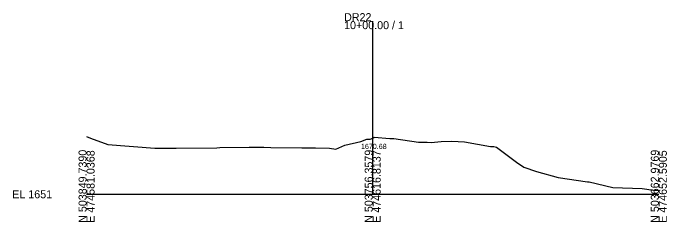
# Model space of a CAD drawing. Extents: x -26 to 1203, y -10 to 9633.
# Drawn here: x -25.7 to 202.8, y -9.7 to 63.5 of the extents above; entities that cross this region are included whole.
import ezdxf

# ---------------------------------------------------------------- set-up
doc = ezdxf.new("R2010")
doc.units = 0
for name, color, linetype in [('Exist Cross Section Cell', 7, 'Continuous'), ('Exist XS Center Line Elevation Label', 7, 'Continuous'), ('Exist XS Ground Line', 7, 'Continuous'), ('Scratch_Level_5', 7, 'Continuous')]:
    doc.layers.add(name, color=color, linetype=linetype)

msp = doc.modelspace()

# ---------------------------------------------------------------- linework, layer by layer
at = {"layer": 'Exist Cross Section Cell'}
for p, q in [((100, 0), (100, 60.64)), ((0, 0), (100, 0)), ((100, 0), (200, 0))]:
    msp.add_line(p, q, dxfattribs=at)
at = {"layer": 'Exist XS Ground Line'}
msp.add_lwpolyline([(0, 20.21), (1.31, 19.71), (7.4, 17.48), (23.86, 16.21), (31.26, 16.15), (45.57, 16.3), (46.55, 16.33), (56.85, 16.51), (61.98, 16.49), (64.39, 16.43), (75.28, 16.27), (79.88, 16.31), (79.98, 16.32), (84.89, 16.15), (87.12, 15.86), (90.22, 17.17), (95.83, 18.46), (98, 19.33), (99.17, 19.25), (100, 19.68), (100.53, 19.98), (105.97, 19.59), (107.34, 19.51), (116.06, 18.25), (119.05, 18.28), (120.48, 18.18), (123.91, 18.45), (127.65, 18.61), (132.05, 18.37), (141.15, 16.79), (142.3, 16.71), (143.23, 16.53), (150.25, 11.2), (152.81, 9.49), (157.28, 7.94), (164.88, 5.84), (175.06, 4.37), (175.69, 4.35), (183.96, 2.33), (194.14, 2.05), (198.15, 1.46), (200, 1.31)], dxfattribs=at)
at = {"layer": 'Scratch_Level_5'}
msp.add_lwpolyline([(0, 20.21), (1.31, 19.71), (7.4, 17.48), (23.86, 16.21), (31.26, 16.15), (45.57, 16.3), (46.55, 16.33), (56.85, 16.51), (61.98, 16.49), (64.39, 16.43), (75.28, 16.27), (79.88, 16.31), (79.98, 16.32), (84.89, 16.15), (87.12, 15.86), (90.22, 17.17), (95.83, 18.46), (98, 19.33), (99.17, 19.25), (100, 19.68), (100.53, 19.98), (105.97, 19.59), (107.34, 19.51), (116.06, 18.25), (119.05, 18.28), (120.48, 18.18), (123.91, 18.45), (127.65, 18.61), (132.05, 18.37), (141.15, 16.79), (142.3, 16.71), (143.23, 16.53), (150.25, 11.2), (152.81, 9.49), (157.28, 7.94), (164.88, 5.84), (175.06, 4.37), (175.69, 4.35), (183.96, 2.33), (194.14, 2.05), (198.15, 1.46), (200, 1.31)], dxfattribs=at)

# ---------------------------------------------------------------- texts
at = {"layer": 'Exist Cross Section Cell'}
for s, p in [('DR22', (90, 60.64)), ('10+00.00 / 1', (90, 57.84)), ('EL 1651', (-26, -1.4))]:
    msp.add_text(s, height=2.8, dxfattribs=at).set_placement(p)
for s, p in [('N 503849.7390', (0, -10)), ('E 474581.0368', (2.8, -10)), ('N 503756.3579', (100, -10)), ('E 474616.8137', (102.8, -10)), ('N 503662.9769', (200, -10)), ('E 474652.5905', (202.8, -10))]:
    msp.add_text(s, height=2.8, rotation=90, dxfattribs=at).set_placement(p)
at = {"layer": 'Exist XS Center Line Elevation Label'}
msp.add_text('1670.68', height=1.8, dxfattribs=at).set_placement((95.9, 15.88))

doc.saveas('drawing.dxf')
